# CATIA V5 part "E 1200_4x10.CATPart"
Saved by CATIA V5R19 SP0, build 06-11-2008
Definition: E 1200_4x10
Nomenclature: E 1200_4x10
Description: PART--DESC
Material "Steel": density 7860 kg/m3, Young's modulus 2e+11 Pa, Poisson ratio 0.266, thermal expansion 1.17e-05 1/K
Bounding box of the stored display mesh (mm): x -49.5 to -42.5, y 17.507 to 24.493, z -21.3 to -7.3
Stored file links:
  G:\UTB\Kombinované\Bakalářská práce\Catia\FORMA\E 1200_4x10.CATPart
  D:\Aplikace\CATIA\Nová složka\win_b64\startup\materials\Catalog.CATMaterial
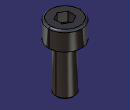
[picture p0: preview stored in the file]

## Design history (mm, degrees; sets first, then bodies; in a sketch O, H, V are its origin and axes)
Body1 "E 2714_32A" (main body)
  Solid1: solid without history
